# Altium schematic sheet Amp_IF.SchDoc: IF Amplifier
size A4; Author: Almela; Revision: 1.2; SheetNumber: 7; SheetTotal: 7
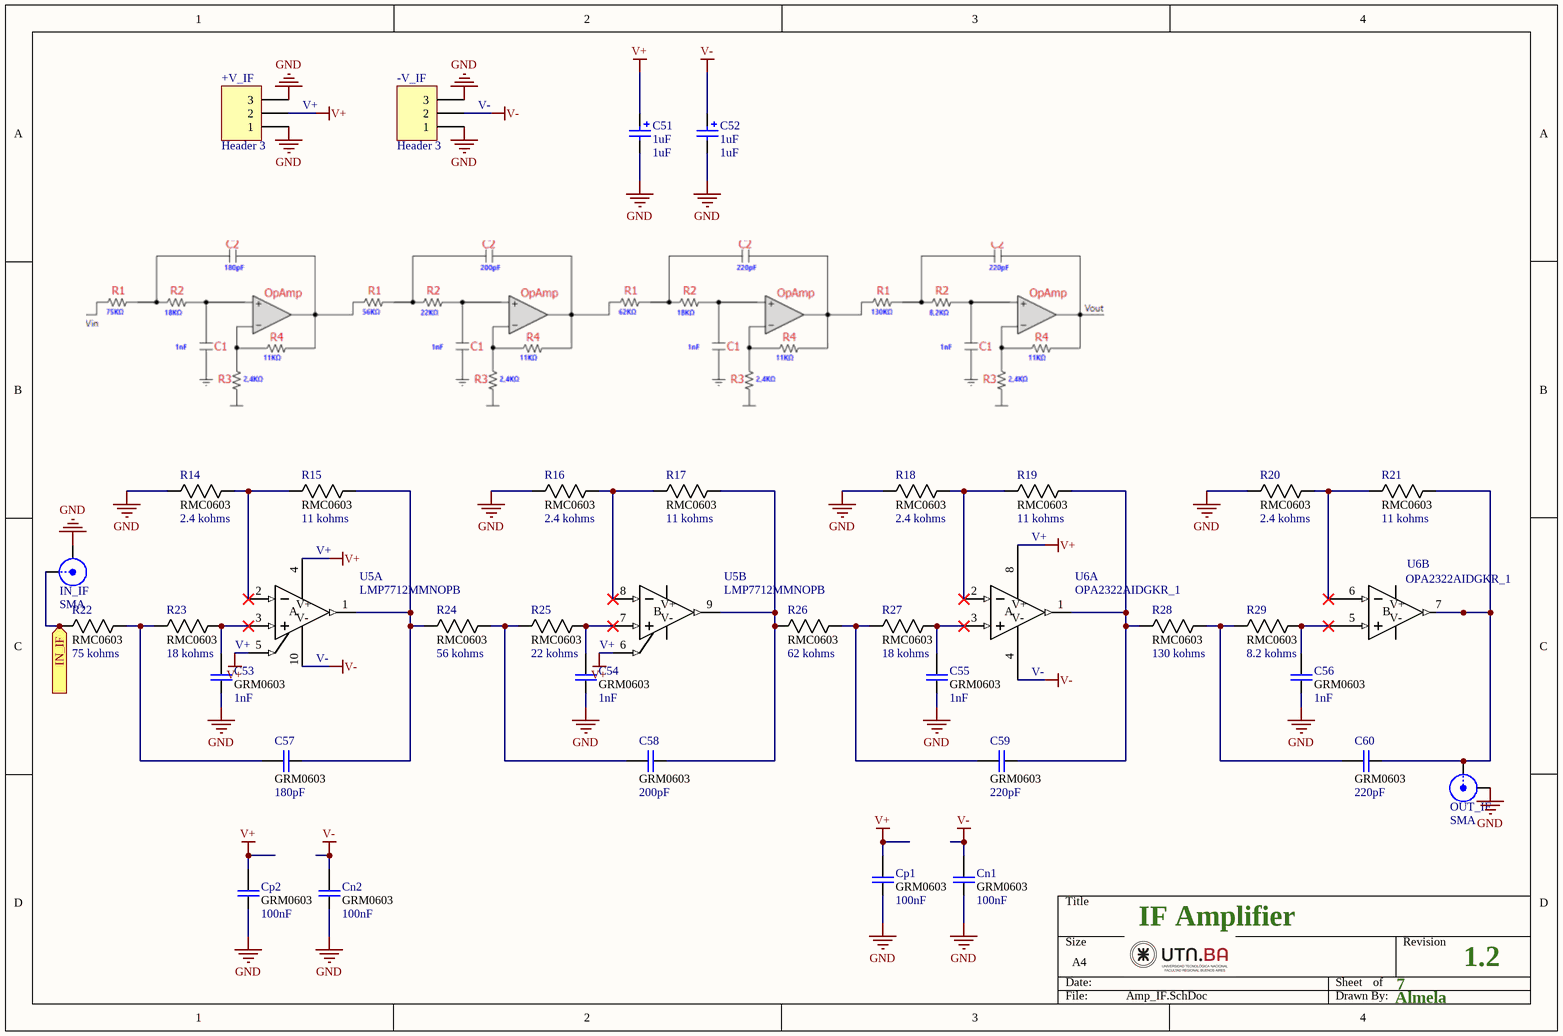
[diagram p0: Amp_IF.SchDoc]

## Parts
+V_IF  Header 3  [HDR1X3]
-V_IF  Header 3  [HDR1X3]
C51  1uF  [6-0805_N]
C52  1uF  [6-0805_N]
C53  value 1nF  footprint: GRM0603  [CAPC1608X90N]  (hidden comment: Cap 0603)
C54  value 1nF  footprint: GRM0603  [CAPC1608X90N]  (hidden comment: Cap 0603)
C55  value 1nF  footprint: GRM0603  [CAPC1608X90N]  (hidden comment: Cap 0603)
C56  value 1nF  footprint: GRM0603  [CAPC1608X90N]  (hidden comment: Cap 0603)
C57  value 180pF  footprint: GRM0603  [CAPC1608X90N]  (hidden comment: Cap 0603)
C58  value 200pF  footprint: GRM0603  [CAPC1608X90N]  (hidden comment: Cap 0603)
C59  value 220pF  footprint: GRM0603  [CAPC1608X90N]  (hidden comment: Cap 0603)
C60  value 220pF  footprint: GRM0603  [CAPC1608X90N]  (hidden comment: Cap 0603)
Cn1  value 100nF  footprint: GRM0603  [CAPC1608X90N]  (hidden comment: Cap 0603)
Cn2  value 100nF  footprint: GRM0603  [CAPC1608X90N]  (hidden comment: Cap 0603)
Cp1  value 100nF  footprint: GRM0603  [CAPC1608X90N]  (hidden comment: Cap 0603)
Cp2  value 100nF  footprint: GRM0603  [CAPC1608X90N]  (hidden comment: Cap 0603)
IN_IF  SMA  [SMA-142-0701-851]
OUT_IF  SMA  [SMA-142-0701-851]
R14  value 2.4 kohms  footprint: RMC0603  [RESC1508X55N]  (hidden comment: Resistor)
R15  value 11 kohms  footprint: RMC0603  [RESC1508X55N]  (hidden comment: Resistor)
R16  value 2.4 kohms  footprint: RMC0603  [RESC1508X55N]  (hidden comment: Resistor)
R17  value 11 kohms  footprint: RMC0603  [RESC1508X55N]  (hidden comment: Resistor)
R18  value 2.4 kohms  footprint: RMC0603  [RESC1508X55N]  (hidden comment: Resistor)
R19  value 11 kohms  footprint: RMC0603  [RESC1508X55N]  (hidden comment: Resistor)
R20  value 2.4 kohms  footprint: RMC0603  [RESC1508X55N]  (hidden comment: Resistor)
R21  value 11 kohms  footprint: RMC0603  [RESC1508X55N]  (hidden comment: Resistor)
R22  value 75 kohms  footprint: RMC0603  [RESC1508X55N]  (hidden comment: Resistor)
R23  value 18 kohms  footprint: RMC0603  [RESC1508X55N]  (hidden comment: Resistor)
R24  value 56 kohms  footprint: RMC0603  [RESC1508X55N]  (hidden comment: Resistor)
R25  value 22 kohms  footprint: RMC0603  [RESC1508X55N]  (hidden comment: Resistor)
R26  value 62 kohms  footprint: RMC0603  [RESC1508X55N]  (hidden comment: Resistor)
R27  value 18 kohms  footprint: RMC0603  [RESC1508X55N]  (hidden comment: Resistor)
R28  value 130 kohms  footprint: RMC0603  [RESC1508X55N]  (hidden comment: Resistor)
R29  value 8.2 kohms  footprint: RMC0603  [RESC1508X55N]  (hidden comment: Resistor)
U5  LMP7712MMNOPB  [SOP50P490X110-10N]  (parts A,B of 2)
U6  OPA2322AIDGKR_1  [DGK8]  (parts A,B of 2)

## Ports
IN_IF (in)

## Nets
GND: +V_IF.1 +V_IF.3 -V_IF.1 -V_IF.3 C51.2 C52.2 C53.1 C54.1 C55.1 C56.1 Cn1.1 Cn2.1 Cp1.1 Cp2.1 IN_IF.2(Y) OUT_IF.2(Y) R14.1 R16.1 R18.1 R20.1
V+: +V_IF.2 C51.1 Cp1.2 Cp2.2 U5.4(V-) U5.5(SD1) U5.6(SD2) U6.8(V+)
V-: -V_IF.2 C52.1 Cn1.2 Cn2.2 U5.10(V+) U6.4(V-)
IN_IF: IN_IF.1(X) R22.1 ; port IN_IF
NetC53_2: C53.2 R23.2 U5.3(IN+)
NetC54_2: C54.2 R25.2 U5.7(IN+)
NetC55_2: C55.2 R27.2 U6.3(IN+)
NetC56_2: C56.2 R29.2 U6.5(INB+)
NetC57_1: C57.1 R15.2 R24.1 U5.1(OUT)
NetC57_2: C57.2 R22.2 R23.1
NetC58_1: C58.1 R17.2 R26.1 U5.9(OUT)
NetC58_2: C58.2 R24.2 R25.1
NetC59_1: C59.1 R19.2 R28.1 U6.1(OUT)
NetC59_2: C59.2 R26.2 R27.1
NetC60_1: C60.1 OUT_IF.1(X) R21.2 U6.7(OUTB)
NetC60_2: C60.2 R28.2 R29.1
NetR14_2: R14.2 R15.1 U5.2(IN-)
NetR16_2: R16.2 R17.1 U5.8(IN-)
NetR18_2: R18.2 R19.1 U6.2(IN-)
NetR20_2: R20.2 R21.1 U6.6(INB-)

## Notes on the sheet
- (near +V_IF) V+
- (near -V_IF) V-
- (near U5) V+
- V+
- (near U5) V-
- (near U6) V-

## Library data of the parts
+V_IF -V_IF = Header 3: Header, 3-Pin
C51 C52 = Cap Pol2_1: Polarized Capacitor (Axial)
C53-C60 Cn1 Cn2 Cp1 Cp2 = Cap: Capacitor GRM18 0603
IN_IF OUT_IF = SMA: SMA Straight Connector
R14-R29 = Resistor: Resistor RMC0603; Mfr_Name: Stackpole International
U5 = LMP7712MMNOPB: No Description Available; Mfr_Name: Texas Instruments; Manufacturer: NationalSemiconductor; Characteristics: LMP7712MM18VPrecisonDualLowNoiseCMOSInputOpAmpwithShutdown; CompType: OpAmpIC; TaMin_C: -400; TaMax_C: 1250; ComponentLink1DescBC: LMP7712Datasheet; ComponentLink2DescA4: LMP7712WebPage; ComponentLink3DescAC: MUB10APackageWebPage
U6 = OPA2322AIDGKR_1: No Description Available; Mfr_Name: Texas Instruments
